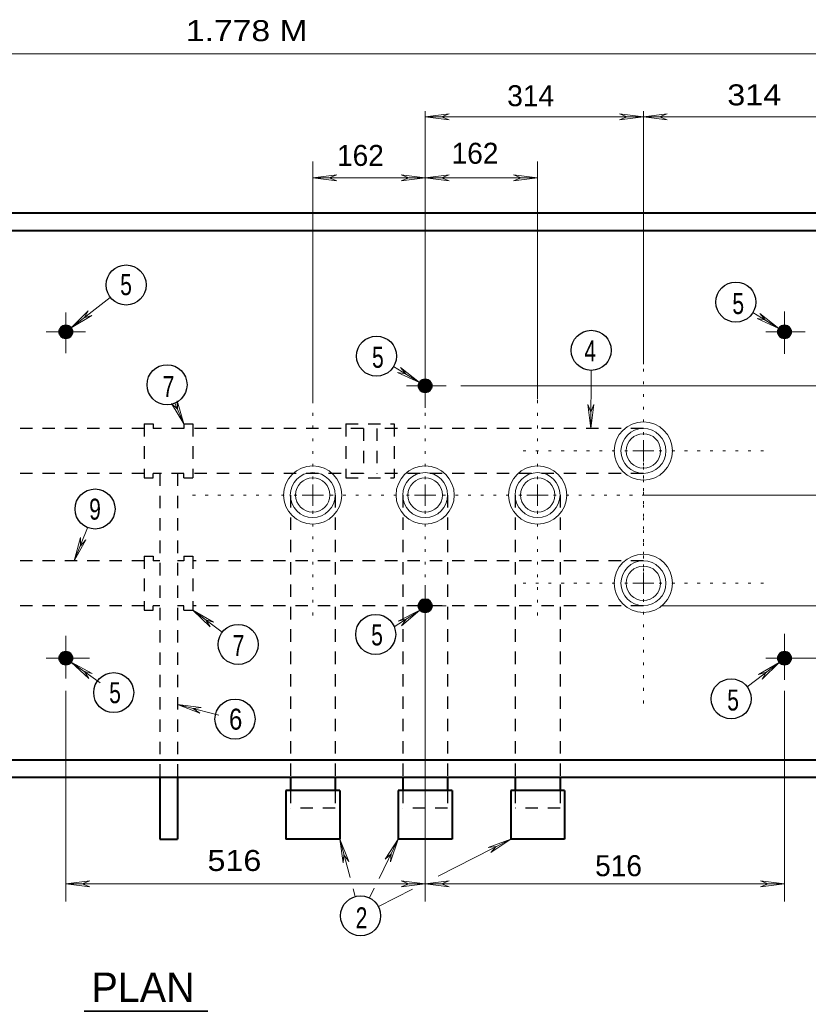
# Model space of a CAD drawing. Extents: x 312583 to 312854, y 144419 to 144597.
# Drawn here: x 312747.96 to 312776.52, y 144464.75 to 144500.65 of the extents above; entities that cross this region are included whole.
import ezdxf
from ezdxf.enums import TextEntityAlignment as Align

# ---------------------------------------------------------------- set-up
doc = ezdxf.new("R2010")
doc.units = 0
doc.header["$LTSCALE"] = 0.3
doc.linetypes.add('DOTTED', pattern=[1.5, 0.3, -1.2])
doc.linetypes.add('SHORT_DASHED', pattern=[2.7, 1.5, -1.2])
for name, color, linetype, lineweight in [('1', 7, 'Continuous', 25), ('2', 7, 'Continuous', 13), ('52', 7, 'Continuous', 25)]:
    doc.layers.add(name, color=color, linetype=linetype, lineweight=lineweight)

msp = doc.modelspace()

# ---------------------------------------------------------------- linework, layer by layer
at = {"layer": '1', "lineweight": 40}
for p, q in [((312746.6716, 144493.6692), (312778.611, 144493.6692)), ((312747.308, 144493.0252), (312777.9746, 144493.0252)), ((312747.308, 144473.8585), (312777.9746, 144473.8585)), ((312746.6716, 144473.2222), (312778.611, 144473.2222)), ((312753.0273, 144473.2222), (312753.0273, 144470.9835)), ((312753.6636, 144473.2222), (312753.6636, 144470.9835)), ((312757.7576, 144473.2222), (312757.7576, 144472.7392)), ((312759.383, 144473.2222), (312759.383, 144472.7392)), ((312761.8286, 144473.2222), (312761.8286, 144472.7392)), ((312763.454, 144473.2222), (312763.454, 144472.7392)), ((312765.8996, 144473.2222), (312765.8996, 144472.7392)), ((312767.5326, 144473.2222), (312767.5326, 144472.7392)), ((312757.5966, 144472.7392), (312757.5966, 144470.9835)), ((312759.544, 144472.7392), (312757.5966, 144472.7392)), ((312759.544, 144472.7392), (312759.544, 144470.9835)), ((312761.6676, 144472.7392), (312761.6676, 144470.9835)), ((312763.615, 144472.7392), (312761.6676, 144472.7392)), ((312763.615, 144472.7392), (312763.615, 144470.9835)), ((312765.7386, 144472.7392), (312765.7386, 144470.9835)), ((312767.686, 144472.7392), (312765.7386, 144472.7392)), ((312767.686, 144472.7392), (312767.686, 144470.9835)), ((312753.0273, 144470.9835), (312753.6636, 144470.9835)), ((312759.544, 144470.9835), (312757.5966, 144470.9835)), ((312763.615, 144470.9835), (312761.6676, 144470.9835)), ((312767.686, 144470.9835), (312765.7386, 144470.9835))]:
    msp.add_line(p, q, dxfattribs=at)
at = {"layer": '1', "linetype": 'SHORT_DASHED'}
for p, q in [((312752.4676, 144485.8568), (312742.5163, 144485.8568)), ((312752.4676, 144486.0178), (312752.4676, 144484.0628)), ((312752.4676, 144486.0178), (312752.782, 144486.0178)), ((312752.782, 144486.0178), (312752.782, 144485.8568)), ((312753.9013, 144485.8568), (312752.782, 144485.8568)), ((312753.9013, 144486.0178), (312753.9013, 144485.8568)), ((312753.9013, 144486.0178), (312754.2233, 144486.0178)), ((312754.2233, 144486.0178), (312754.2233, 144484.0628)), ((312760.4026, 144485.8568), (312754.2233, 144485.8568)), ((312759.7663, 144486.0178), (312761.522, 144486.0178)), ((312759.7663, 144486.0178), (312759.7663, 144484.0628)), ((312760.4026, 144485.8568), (312760.4026, 144484.2238)), ((312760.8856, 144485.8568), (312760.8856, 144484.2238)), ((312770.5456, 144485.8568), (312760.8856, 144485.8568)), ((312761.522, 144486.0178), (312761.522, 144484.0628)), ((312752.4676, 144484.2238), (312742.5163, 144484.2238)), ((312752.4676, 144484.0628), (312752.782, 144484.0628)), ((312752.782, 144484.0628), (312752.782, 144484.2238)), ((312753.9013, 144484.2238), (312752.782, 144484.2238)), ((312753.0273, 144484.2238), (312753.0273, 144473.2222)), ((312753.6636, 144484.2238), (312753.6636, 144473.2222)), ((312753.9013, 144484.0628), (312753.9013, 144484.2238)), ((312753.9013, 144484.0628), (312754.2233, 144484.0628)), ((312760.4026, 144484.2238), (312754.2233, 144484.2238)), ((312759.7663, 144484.0628), (312761.522, 144484.0628)), ((312770.5456, 144484.2238), (312760.8856, 144484.2238)), ((312757.7576, 144483.4418), (312757.7576, 144473.2222)), ((312759.383, 144483.4418), (312759.383, 144473.2222)), ((312761.8286, 144483.4418), (312761.8286, 144473.2222)), ((312763.454, 144483.4418), (312763.454, 144473.2222)), ((312765.8996, 144483.4418), (312765.8996, 144473.2222)), ((312767.5326, 144483.4418), (312767.5326, 144473.2222)), ((312752.4676, 144481.0652), (312740.2776, 144481.0652)), ((312752.4676, 144481.2262), (312752.4676, 144479.2712)), ((312752.4676, 144481.2262), (312752.782, 144481.2262)), ((312752.782, 144481.2262), (312752.782, 144481.0652)), ((312753.0273, 144481.0652), (312752.782, 144481.0652)), ((312753.9013, 144481.0652), (312753.6636, 144481.0652)), ((312753.9013, 144481.2262), (312753.9013, 144481.0652)), ((312753.9013, 144481.2262), (312754.2233, 144481.2262)), ((312754.2233, 144481.2262), (312754.2233, 144479.2712)), ((312770.5456, 144481.0652), (312754.2233, 144481.0652)), ((312752.4676, 144479.4322), (312740.2776, 144479.4322)), ((312752.4676, 144479.2712), (312752.782, 144479.2712)), ((312752.782, 144479.2712), (312752.782, 144479.4322)), ((312753.0273, 144479.4322), (312752.782, 144479.4322)), ((312753.9013, 144479.4322), (312753.6636, 144479.4322)), ((312753.9013, 144479.2712), (312753.9013, 144479.4322)), ((312753.9013, 144479.2712), (312754.2233, 144479.2712)), ((312770.5456, 144479.4322), (312754.2233, 144479.4322)), ((312757.7576, 144472.7392), (312757.7576, 144472.1028)), ((312759.383, 144472.7392), (312759.383, 144472.1028)), ((312761.8286, 144472.7392), (312761.8286, 144472.1028)), ((312763.454, 144472.7392), (312763.454, 144472.1028)), ((312765.8996, 144472.7392), (312765.8996, 144472.1028)), ((312767.5326, 144472.7392), (312767.5326, 144472.1028)), ((312759.383, 144472.1028), (312757.7576, 144472.1028)), ((312763.454, 144472.1028), (312761.8286, 144472.1028)), ((312767.5326, 144472.1028), (312765.8996, 144472.1028))]:
    msp.add_line(p, q, dxfattribs=at)
at = {"layer": '1', "lineweight": 40}
for centre, radius in [((312749.6239, 144489.3535), 0.2396), ((312749.6239, 144489.3535), 0.2156), ((312749.6239, 144489.3535), 0.1941), ((312749.6239, 144489.3535), 0.1747), ((312749.6239, 144489.3535), 0.1572), ((312749.6239, 144489.3535), 0.1415), ((312749.6239, 144489.3535), 0.1273), ((312749.6239, 144489.3535), 0.1146), ((312749.6239, 144489.3535), 0.1031), ((312749.6239, 144489.3535), 0.0928), ((312749.6239, 144489.3535), 0.0835), ((312749.6239, 144489.3535), 0.0752), ((312749.6239, 144489.3535), 0.0677), ((312749.6239, 144489.3535), 0.0609), ((312749.6239, 144489.3535), 0.0548), ((312775.6587, 144489.3535), 0.2396), ((312775.6587, 144489.3535), 0.2156), ((312775.6587, 144489.3535), 0.1941), ((312775.6587, 144489.3535), 0.1747), ((312775.6587, 144489.3535), 0.1572), ((312775.6587, 144489.3535), 0.1415), ((312775.6587, 144489.3535), 0.1273), ((312775.6587, 144489.3535), 0.1146), ((312775.6587, 144489.3535), 0.1031), ((312775.6587, 144489.3535), 0.0928), ((312775.6587, 144489.3535), 0.0835), ((312775.6587, 144489.3535), 0.0752), ((312775.6587, 144489.3535), 0.0677), ((312775.6587, 144489.3535), 0.0609), ((312775.6587, 144489.3535), 0.0548), ((312749.6239, 144477.534), 0.2396), ((312749.6239, 144477.534), 0.2156), ((312749.6239, 144477.534), 0.1941), ((312749.6239, 144477.534), 0.1747), ((312749.6239, 144477.534), 0.1572), ((312749.6239, 144477.534), 0.1415), ((312749.6239, 144477.534), 0.1273), ((312749.6239, 144477.534), 0.1146), ((312749.6239, 144477.534), 0.1031), ((312749.6239, 144477.534), 0.0928), ((312749.6239, 144477.534), 0.0835), ((312749.6239, 144477.534), 0.0752), ((312749.6239, 144477.534), 0.0677), ((312749.6239, 144477.534), 0.0609), ((312749.6239, 144477.534), 0.0548), ((312775.6587, 144477.534), 0.2396), ((312775.6587, 144477.534), 0.2156), ((312775.6587, 144477.534), 0.1941), ((312775.6587, 144477.534), 0.1747), ((312775.6587, 144477.534), 0.1572), ((312775.6587, 144477.534), 0.1415), ((312775.6587, 144477.534), 0.1273), ((312775.6587, 144477.534), 0.1146), ((312775.6587, 144477.534), 0.1031), ((312775.6587, 144477.534), 0.0928), ((312775.6587, 144477.534), 0.0835), ((312775.6587, 144477.534), 0.0752), ((312775.6587, 144477.534), 0.0677), ((312775.6587, 144477.534), 0.0609), ((312775.6587, 144477.534), 0.0548)]:
    msp.add_circle(centre, radius, dxfattribs=at)
at = {"layer": '1', "lineweight": 13}
for centre, radius in [((312770.5476, 144485.041), 1.0542), ((312770.5476, 144485.041), 0.8146), ((312770.5476, 144485.041), 0.6232), ((312758.5684, 144483.4438), 1.0542), ((312762.6413, 144483.4438), 1.0542), ((312766.7142, 144483.4438), 1.0542), ((312758.5684, 144483.4438), 0.8146), ((312758.5684, 144483.4438), 0.6232), ((312762.6413, 144483.4438), 0.8146), ((312762.6413, 144483.4438), 0.6232), ((312766.7142, 144483.4438), 0.8146), ((312766.7142, 144483.4438), 0.6232), ((312770.5476, 144480.2493), 1.0542), ((312770.5476, 144480.2493), 0.8146), ((312770.5476, 144480.2493), 0.6232)]:
    msp.add_circle(centre, radius, dxfattribs=at)
at = {"layer": '2'}
for p, q in [((312733.8913, 144499.4268), (312778.611, 144499.4268)), ((312762.6413, 144486.7998), (312762.6413, 144497.3415)), ((312762.6413, 144497.1422), (312763.5076, 144497.2495)), ((312763.5076, 144497.2495), (312763.2316, 144497.1422)), ((312769.6793, 144497.2495), (312769.9553, 144497.1422)), ((312770.5456, 144497.1422), (312769.6793, 144497.2495)), ((312770.5456, 144488.1798), (312770.5456, 144497.3415)), ((312770.5456, 144497.1422), (312771.412, 144497.2495)), ((312771.412, 144497.2495), (312771.136, 144497.1422)), ((312762.6413, 144497.1422), (312763.5076, 144497.0348)), ((312763.5076, 144497.0348), (312763.2316, 144497.1422)), ((312769.6793, 144497.0348), (312769.9553, 144497.1422)), ((312770.5456, 144497.1422), (312769.6793, 144497.0348)), ((312770.5456, 144497.1422), (312771.412, 144497.0348)), ((312771.412, 144497.0348), (312771.136, 144497.1422)), ((312758.5703, 144486.8382), (312758.5703, 144495.5168)), ((312766.7123, 144486.9148), (312766.7123, 144495.5168)), ((312758.5703, 144494.9342), (312759.4366, 144495.0415)), ((312758.5703, 144494.9342), (312762.6413, 144494.9342)), ((312758.5703, 144494.9342), (312759.4366, 144494.8268)), ((312759.4366, 144495.0415), (312759.1606, 144494.9342)), ((312759.4366, 144494.8268), (312759.1606, 144494.9342)), ((312761.775, 144495.0415), (312762.051, 144494.9342)), ((312762.6413, 144494.9342), (312761.775, 144495.0415)), ((312761.775, 144494.8268), (312762.051, 144494.9342)), ((312762.6413, 144494.9342), (312761.775, 144494.8268)), ((312762.6413, 144494.9342), (312763.5076, 144495.0415)), ((312762.6413, 144494.9342), (312766.7123, 144494.9342)), ((312762.6413, 144494.9342), (312763.5076, 144494.8268)), ((312763.5076, 144495.0415), (312763.2316, 144494.9342)), ((312763.5076, 144494.8268), (312763.2316, 144494.9342)), ((312765.846, 144495.0415), (312766.122, 144494.9342)), ((312766.7123, 144494.9342), (312765.846, 144495.0415)), ((312765.846, 144494.8268), (312766.122, 144494.9342)), ((312766.7123, 144494.9342), (312765.846, 144494.8268)), ((312751.2333, 144490.6025), (312749.815, 144489.4985)), ((312749.6233, 144490.0582), (312749.6233, 144488.5785)), ((312749.815, 144489.4985), (312750.4283, 144490.1195)), ((312750.4283, 144490.1195), (312750.2826, 144489.8588)), ((312774.517, 144490.0505), (312775.4523, 144489.4755)), ((312774.77, 144490.0198), (312774.954, 144489.7898)), ((312775.4523, 144489.4755), (312774.77, 144490.0198)), ((312775.6593, 144490.0888), (312775.6593, 144488.5555)), ((312749.815, 144489.4985), (312750.5663, 144489.9432)), ((312750.5663, 144489.9432), (312750.2826, 144489.8588)), ((312774.6626, 144489.8358), (312774.954, 144489.7898)), ((312775.4523, 144489.4755), (312774.6626, 144489.8358)), ((312748.9103, 144489.3528), (312750.3363, 144489.3528)), ((312774.9846, 144489.3528), (312776.4106, 144489.3528)), ((312768.652, 144487.9575), (312768.6366, 144485.8568)), ((312763.937, 144487.3978), (312782.59, 144487.3978)), ((312753.656, 144486.8535), (312753.6636, 144486.5545)), ((312753.9013, 144486.0178), (312753.656, 144486.8535)), ((312753.4566, 144486.7615), (312753.6636, 144486.5545)), ((312753.9013, 144486.0178), (312753.4566, 144486.7615)), ((312753.5716, 144486.7692), (312753.9013, 144486.0178)), ((312768.537, 144486.7232), (312768.6443, 144486.4472)), ((312768.6366, 144485.8568), (312768.537, 144486.7232)), ((312768.6366, 144485.8568), (312768.7516, 144486.7232)), ((312768.7516, 144486.7232), (312768.6443, 144486.4472)), ((312770.5456, 144485.0442), (312770.5456, 144485.4275)), ((312770.5456, 144485.0442), (312770.1623, 144485.0442)), ((312770.5456, 144485.0442), (312770.929, 144485.0442)), ((312770.5456, 144485.0442), (312770.5456, 144484.6608)), ((312758.5703, 144483.4418), (312758.5703, 144483.8252)), ((312762.6413, 144483.4418), (312762.6413, 144483.8252)), ((312766.7123, 144483.4418), (312766.7123, 144483.8252)), ((312758.5703, 144483.4418), (312758.187, 144483.4418)), ((312758.5703, 144483.4418), (312758.9536, 144483.4418)), ((312758.5703, 144483.4418), (312758.5703, 144483.0585)), ((312762.6413, 144483.4418), (312762.258, 144483.4418)), ((312762.6413, 144483.4418), (312763.0246, 144483.4418)), ((312762.6413, 144483.4418), (312762.6413, 144483.0585)), ((312766.7123, 144483.4418), (312766.329, 144483.4418)), ((312766.7123, 144483.4418), (312767.0956, 144483.4418)), ((312766.7123, 144483.4418), (312766.7123, 144483.0585)), ((312770.5993, 144483.4418), (312788.547, 144483.4418)), ((312750.413, 144482.2612), (312749.93, 144481.0652)), ((312749.93, 144481.0652), (312750.1523, 144481.9085)), ((312749.93, 144481.0652), (312750.3516, 144481.8242)), ((312750.1523, 144481.9085), (312750.1523, 144481.6095)), ((312750.3516, 144481.8242), (312750.1523, 144481.6095)), ((312770.5456, 144480.2525), (312770.5456, 144480.6358)), ((312770.5456, 144480.2525), (312770.1623, 144480.2525)), ((312770.5456, 144480.2525), (312770.929, 144480.2525)), ((312770.5456, 144480.2525), (312770.5456, 144479.8692)), ((312755.289, 144478.4738), (312754.2233, 144479.2712)), ((312754.2233, 144479.2712), (312754.852, 144478.6655)), ((312754.2233, 144479.2712), (312754.9746, 144478.8418)), ((312762.6413, 144479.4322), (312762.6413, 144468.7295)), ((312771.182, 144479.4322), (312782.59, 144479.4322)), ((312754.852, 144478.6655), (312754.691, 144478.9185)), ((312754.9746, 144478.8418), (312754.691, 144478.9185)), ((312749.6233, 144478.3435), (312749.6233, 144476.7948)), ((312775.6593, 144478.4125), (312775.6593, 144476.7488)), ((312748.9103, 144477.5308), (312750.482, 144477.5308)), ((312774.9846, 144477.5308), (312785.3576, 144477.5308)), ((312750.8653, 144476.6415), (312749.8226, 144477.3928)), ((312749.8226, 144477.3928), (312750.459, 144476.8025)), ((312749.8226, 144477.3928), (312750.5816, 144476.9788)), ((312774.3023, 144476.5035), (312775.4676, 144477.3852)), ((312775.4676, 144477.3852), (312774.7163, 144476.9482)), ((312775.4676, 144477.3852), (312774.8466, 144476.7795)), ((312750.459, 144476.8025), (312750.298, 144477.0478)), ((312750.5816, 144476.9788), (312750.298, 144477.0478)), ((312774.7163, 144476.9482), (312775, 144477.0325)), ((312774.8466, 144476.7795), (312775, 144477.0325)), ((312749.6233, 144476.3502), (312749.6233, 144468.7295)), ((312775.6593, 144476.3502), (312775.6593, 144468.7295)), ((312755.1663, 144475.4762), (312753.6636, 144475.8595)), ((312753.6636, 144475.8595), (312754.4763, 144475.5452)), ((312753.6636, 144475.8595), (312754.53, 144475.7522)), ((312754.53, 144475.7522), (312754.2386, 144475.7138)), ((312754.4763, 144475.5452), (312754.2386, 144475.7138)), ((312759.544, 144470.9835), (312759.6666, 144470.1248)), ((312759.544, 144470.9835), (312759.8736, 144470.1785)), ((312759.544, 144470.9835), (312759.9196, 144469.5958)), ((312760.97, 144469.5575), (312761.6676, 144470.9835)), ((312761.6676, 144470.9835), (312761.1923, 144470.2552)), ((312761.6676, 144470.9835), (312761.384, 144470.1632)), ((312765.7386, 144470.9835), (312763.1166, 144469.6418)), ((312765.7386, 144470.9835), (312764.9183, 144470.6845)), ((312764.9183, 144470.6845), (312765.2173, 144470.7152)), ((312765.7386, 144470.9835), (312765.018, 144470.4928)), ((312765.018, 144470.4928), (312765.2173, 144470.7152)), ((312759.6666, 144470.1248), (312759.6973, 144470.4162)), ((312759.8736, 144470.1785), (312759.6973, 144470.4162)), ((312761.1923, 144470.2552), (312761.407, 144470.4545)), ((312761.384, 144470.1632), (312761.407, 144470.4545)), ((312749.6233, 144469.3658), (312750.4896, 144469.4732)), ((312749.6233, 144469.3658), (312750.4896, 144469.2585)), ((312750.4896, 144469.4732), (312750.2136, 144469.3658)), ((312750.4896, 144469.2585), (312750.2136, 144469.3658)), ((312760.625, 144468.8522), (312760.7936, 144469.2048)), ((312761.775, 144469.4732), (312762.051, 144469.3658)), ((312762.6413, 144469.3658), (312761.775, 144469.4732)), ((312761.775, 144469.2585), (312762.051, 144469.3658)), ((312762.6413, 144469.3658), (312761.775, 144469.2585)), ((312762.6413, 144469.3658), (312763.5076, 144469.4732)), ((312762.6413, 144469.3658), (312763.5076, 144469.2585)), ((312763.5076, 144469.4732), (312763.2316, 144469.3658)), ((312763.5076, 144469.2585), (312763.2316, 144469.3658)), ((312774.793, 144469.4732), (312775.069, 144469.3658)), ((312775.6593, 144469.3658), (312774.793, 144469.4732)), ((312774.793, 144469.2585), (312775.069, 144469.3658)), ((312775.6593, 144469.3658), (312774.793, 144469.2585)), ((312760.0346, 144469.1818), (312760.1113, 144468.9058)), ((312762.1813, 144469.1665), (312760.947, 144468.5378))]:
    msp.add_line(p, q, dxfattribs=at)
at = {"layer": '2', "linetype": 'DOTTED'}
for p, q in [((312770.5456, 144485.6192), (312770.5456, 144489.4525)), ((312758.5703, 144484.0168), (312758.5703, 144487.8502)), ((312762.6413, 144484.0168), (312762.6413, 144487.8502)), ((312766.7123, 144484.0168), (312766.7123, 144487.8502)), ((312769.9706, 144485.0442), (312766.1373, 144485.0442)), ((312771.1206, 144485.0442), (312774.954, 144485.0442)), ((312770.5456, 144480.8275), (312770.5456, 144484.6608)), ((312770.5456, 144484.4692), (312770.5456, 144480.6358)), ((312757.9953, 144483.4418), (312754.162, 144483.4418)), ((312762.0663, 144483.4418), (312758.233, 144483.4418)), ((312766.1373, 144483.4418), (312762.304, 144483.4418)), ((312767.2873, 144483.4418), (312771.1206, 144483.4418)), ((312758.5703, 144482.8668), (312758.5703, 144479.0335)), ((312762.6413, 144482.8668), (312762.6413, 144479.0335)), ((312766.7123, 144482.8668), (312766.7123, 144479.0335)), ((312769.9706, 144480.2525), (312766.1373, 144480.2525)), ((312771.1206, 144480.2525), (312774.954, 144480.2525)), ((312770.5456, 144479.6775), (312770.5456, 144475.8442))]:
    msp.add_line(p, q, dxfattribs=at)
at = {"layer": '2', "lineweight": 35}
msp.add_line((312750.2876, 144464.7524), (312754.7672, 144464.7524), dxfattribs=at)
at = {"layer": '2'}
for points in [[(312762.6413, 144497.1422), (312770.5456, 144497.1422), (312778.611, 144497.1422)], [(312749.6233, 144469.3658), (312762.6413, 144469.3658), (312775.6593, 144469.3658)]]:
    msp.add_lwpolyline(points, dxfattribs=at)
at = {"layer": '2', "lineweight": 25}
for centre in [(312751.8089, 144491.0504), (312773.896, 144490.4306), (312768.6558, 144488.6839), (312753.2903, 144487.4386), (312750.6819, 144482.9371), (312755.8659, 144478.0349), (312751.3579, 144476.2882), (312773.7273, 144476.0627), (312755.7528, 144475.3305), (312760.3017, 144468.205)]:
    msp.add_circle(centre, 0.7254, dxfattribs=at)
at = {"layer": '52', "lineweight": 13}
for p, q in [((312761.499, 144488.0955), (312762.4343, 144487.5205)), ((312761.6446, 144487.8808), (312761.936, 144487.8272)), ((312762.4343, 144487.5205), (312761.6446, 144487.8808)), ((312761.752, 144488.0648), (312761.936, 144487.8272)), ((312762.4343, 144487.5205), (312761.752, 144488.0648)), ((312762.6413, 144488.1338), (312762.6413, 144486.6005)), ((312761.9666, 144487.3978), (312763.4003, 144487.3978)), ((312762.6413, 144480.1758), (312762.6413, 144478.6348)), ((312761.522, 144478.6655), (312762.4573, 144479.2788)), ((312762.442, 144479.2712), (312761.66, 144478.8802)), ((312762.442, 144479.2712), (312761.7826, 144478.7038)), ((312761.9666, 144479.4322), (312763.4003, 144479.4322)), ((312761.66, 144478.8802), (312761.9513, 144478.9492)), ((312761.7826, 144478.7038), (312761.9513, 144478.9492))]:
    msp.add_line(p, q, dxfattribs=at)
at = {"layer": '52'}
for centre in [(312760.8786, 144488.4744), (312760.8492, 144478.3953)]:
    msp.add_circle(centre, 0.7254, dxfattribs=at)
at = {"layer": '52', "lineweight": 40}
for centre, radius in [((312762.6413, 144487.3972), 0.2396), ((312762.6413, 144487.3972), 0.2156), ((312762.6413, 144487.3972), 0.1941), ((312762.6413, 144487.3972), 0.1747), ((312762.6413, 144487.3972), 0.1572), ((312762.6413, 144487.3972), 0.1415), ((312762.6413, 144487.3972), 0.1273), ((312762.6413, 144487.3972), 0.1146), ((312762.6413, 144487.3972), 0.1031), ((312762.6413, 144487.3972), 0.0928), ((312762.6413, 144487.3972), 0.0835), ((312762.6413, 144487.3972), 0.0752), ((312762.6413, 144487.3972), 0.0677), ((312762.6413, 144487.3972), 0.0609), ((312762.6413, 144487.3972), 0.0548), ((312762.6413, 144479.4347), 0.2396), ((312762.6413, 144479.4347), 0.2156), ((312762.6413, 144479.4347), 0.1941), ((312762.6413, 144479.4347), 0.1747), ((312762.6413, 144479.4347), 0.1572), ((312762.6413, 144479.4347), 0.1415), ((312762.6413, 144479.4347), 0.1273), ((312762.6413, 144479.4347), 0.1146), ((312762.6413, 144479.4347), 0.1031), ((312762.6413, 144479.4347), 0.0928), ((312762.6413, 144479.4347), 0.0835), ((312762.6413, 144479.4347), 0.0752), ((312762.6413, 144479.4347), 0.0677), ((312762.6413, 144479.4347), 0.0609), ((312762.6413, 144479.4347), 0.0548)]:
    msp.add_circle(centre, radius, dxfattribs=at)

# ---------------------------------------------------------------- texts
at = {"layer": '2'}
for s, width, p in [('1.778 M', 1.2, (312753.9732, 144499.8818)), ('314 ', 1.15, (312773.5868, 144497.5554)), ('5', 0.75, (312751.5929, 144490.6827)), ('5', 0.75, (312773.7704, 144489.9974)), ('4', 0.75, (312768.4083, 144488.2853)), ('7', 0.75, (312753.1291, 144486.9894)), ('9', 0.75, (312750.4695, 144482.5533)), ('7', 0.75, (312755.6665, 144477.6183)), ('5', 0.75, (312751.1945, 144475.9063)), ('5', 0.75, (312773.5837, 144475.6404)), ('6', 0.85, (312755.5359, 144474.9479)), ('516 ', 1.15, (312754.7555, 144469.8296)), ('2', 0.75, (312760.1235, 144467.7538))]:
    msp.add_text(s, height=0.76, dxfattribs=dict(at, width=width)).set_placement(p)
for s, p in [('314', (312765.6141, 144497.5253)), ('162', (312759.4486, 144495.3632)), ('162', (312763.5993, 144495.4409)), ('516', (312768.7986, 144469.641))]:
    msp.add_text(s, height=0.76, dxfattribs=at).set_placement(p)
msp.add_text('PLAN', height=1.07, dxfattribs=at).set_placement((312752.4218, 144465.0828), align=Align.CENTER)
at = {"layer": '52', "width": 0.75}
for p in [(312760.7165, 144488.0527), (312760.6858, 144477.9967)]:
    msp.add_text('5', height=0.76, dxfattribs=at).set_placement(p)

doc.saveas('drawing.dxf')
